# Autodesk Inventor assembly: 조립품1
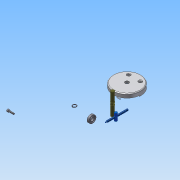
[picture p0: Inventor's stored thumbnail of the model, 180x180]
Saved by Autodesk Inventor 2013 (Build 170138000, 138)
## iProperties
Created: 2015-04
Part Number: 조립품1
Document SubType Name: Assembly
Designer: Administrator
Author: Administrator
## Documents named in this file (10)
- C:\Users\Administrator\Desktop\450406V1006\조립품1.iam
- C:\Users\Administrator\Desktop\450406V1006\M 10 x 35.ipt
- C:\Users\Administrator\Desktop\450406V1006\덮개.ipt
- C:\Users\Administrator\Desktop\450406V1006\멈춤링.ipt
- C:\Users\Administrator\Desktop\450406V1006\베어링62_22.ipt
- C:\Users\Administrator\Desktop\450406V1006\본체.ipt
- C:\Users\Administrator\Desktop\450406V1006\슬라이더.ipt
- C:\Users\Administrator\Desktop\450406V1006\슬라이더2.ipt
- C:\Users\Administrator\Desktop\450406V1006\축.ipt
- C:\Users\Administrator\Desktop\450406V1006\평행핀.ipt
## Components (1 placed, 1 different names)
1. M 10 x 35:1
